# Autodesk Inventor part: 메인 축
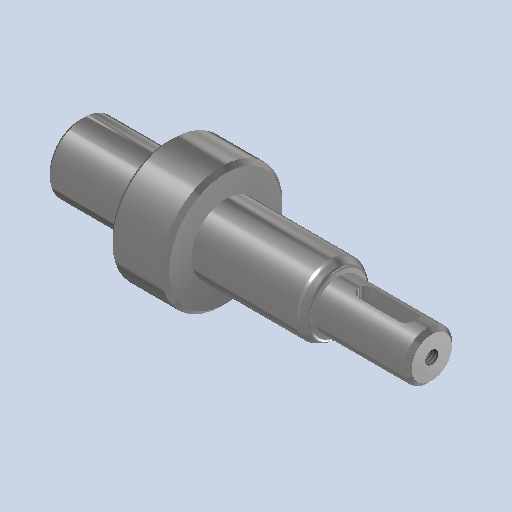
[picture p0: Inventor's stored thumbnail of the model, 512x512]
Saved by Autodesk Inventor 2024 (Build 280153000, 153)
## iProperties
Created: 2016-04
Part Number: 메인 축
Document SubType Name: Modeling
Designer: mdu
Density: 7.86 g/cm^3
Mass: 230.24 g
Surface Area: 74.3518 cm^2
Volume: 29.2926 cm^3
Material: 강철, 연강
Appearance: 반광택
Author: mdu
Revision Number: 1
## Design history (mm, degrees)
sketch "스케치1"
  geometry: L1 (10.497, -57.5)-(97.497, -57.5); L2 (10.497, -66)-(32.497, -66); L3 (32.497, -72.5)-(46.5, -72.5); L4 (46.5, -66)-(74.497, -66); L5 (97.497, -63.5)-(97.497, -57.5); L6 (10.497, -66)-(10.497, -57.5); L7 (46.5, -69.749)-(46.5, -45.251) reference; L8 (46.5, -72.5)-(46.5, -66); L9 (32.497, -72.5)-(32.497, -66); L10 (32.497, -35)-(32.497, -80) reference; L11 (97.497, -63.5)-(74.497, -63.5); L12 (74.497, -63.5)-(74.497, -66); 3 further points
  constraints: 20 end point, 4 perpendicular, 3 point on line, 2 parallel, 1 collinear, 1 horizontal, 1 midpoint
  dimensions: "d0" = 17 diameter of L4 L1; "d1" = 30 diameter of L3 L1; "d2" = 22 distance of L2.start L2.end; "d5" = 17 diameter of L2 L1; "d19" = 65 distance between parallel lines of L5 L9; "d21" = 50.99692 distance between parallel lines of L5 L8 (derived); "d22" = 23 distance between parallel lines of L5 L12; "d23" = 12 diameter of L11 L1
revolve "회전1" sketch "스케치1" stored, may be unused: angle "d4" = 90 deg
chamfer "모따기1" distance "d6" = 1; stored, may be unused: second distance "d7" = 2, angle "d8" = 45 deg
node "작업 평면1"
sketch "스케치2"
  geometry: L1 (10.497, -65)-(10.497, -50) reference; L2 (16.997, -55)-(25.997, -55); L3 (25.997, -60)-(16.997, -60); A1 r 2.5 centre (25.997, -57.5) between (25.997, -60) and (25.997, -55); A2 r 2.5 centre (16.997, -57.5) between (16.997, -55) and (16.997, -60); 2 further points
  constraints: 4 end point, 4 point on circle, 4 tangent, 2 centre point, 1 horizontal alignment, 1 midpoint, 1 parallel, 1 perpendicular
  dimensions: "d9" = 5 distance between parallel lines of L3 L2; "d10" = 14 dimension on A1 A2; "d11" = 4 distance edge to line of A2 L1
extrude "돌출1" cut sketch "스케치2" distance "d12" = 3; taper "d13" = 0 deg
node "작업 평면2"
sketch "스케치3"
  geometry: L1 (91.497, -55.5)-(81.497, -55.5); L2 (81.497, -59.5)-(91.497, -59.5); L3 (97.497, -52.5)-(97.497, -62.5) reference; A1 r 2 centre (81.497, -57.5) between (81.497, -55.5) and (81.497, -59.5); A2 r 2 centre (91.497, -57.5) between (91.497, -59.5) and (91.497, -55.5); 4 further points
  constraints: 4 end point, 4 point on circle, 4 tangent, 2 centre point, 2 horizontal, 2 point on line, 1 horizontal alignment, 1 midpoint, 1 vertical alignment
  dimensions: "d32" = 14 dimension on A2 A1; "d34" = 4 distance edge to line of A2 L3; "d35" = 4 distance between parallel lines of L2 L1
extrude "돌출2" cut sketch "스케치3" distance "d16" = 2.5; taper "d17" = 0 deg
sketch "스케치4"
  geometry: L1 (74.497, -50.05)-(72.678, -49); L2 (74.497, -49)-(46.5, -49) reference; L3 (74.497, -49)-(74.497, -66) reference; L4 (74.497, -66)-(46.5, -66) reference; L5 (74.497, -57.5)-(60.711, -57.5); 1 further point
  constraints: 4 end point, 2 point on line, 1 midpoint, 1 parallel
  dimensions: "d24" = 14.9 diameter of L1.start L5; "d26" = 30 deg angle of L2 L1
revolve "회전2" sketch "스케치4" stored, may be unused: angle "d28" = 90 deg
fillet "모깎기1" dims "d29" = 1
fillet "모깎기2" dims "d30" = 2
hole "구멍1" diameter "d38" = 3.242; stored, may be unused: countersink angle "d42" = 90 deg, drill point angle "d44" = 118 deg; dims "d39" = 8, "d40" = 4, "d41" = 2, "d43" = 10, "d45" = 10, "d46" = 10
node "솔리드1"
node "참조4"
node "참조5"
other parameters: "d20" = 6, "d47" = -8.5
